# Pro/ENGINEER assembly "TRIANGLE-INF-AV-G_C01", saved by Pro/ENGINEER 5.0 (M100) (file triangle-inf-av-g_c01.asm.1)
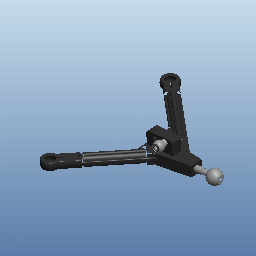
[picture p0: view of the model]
Units: millimeter Newton Second (mmNs); MM, TONNE, HOURS

Other components: 80657301-TRI_INF_AV_COMPL_C01, 80462600-ROTULE_D14_C01, 80657301-TRIANG_AV_INF_COMP_C01

Other named items: A-DROITE, A-DESSUS, A-FACE, A-R0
